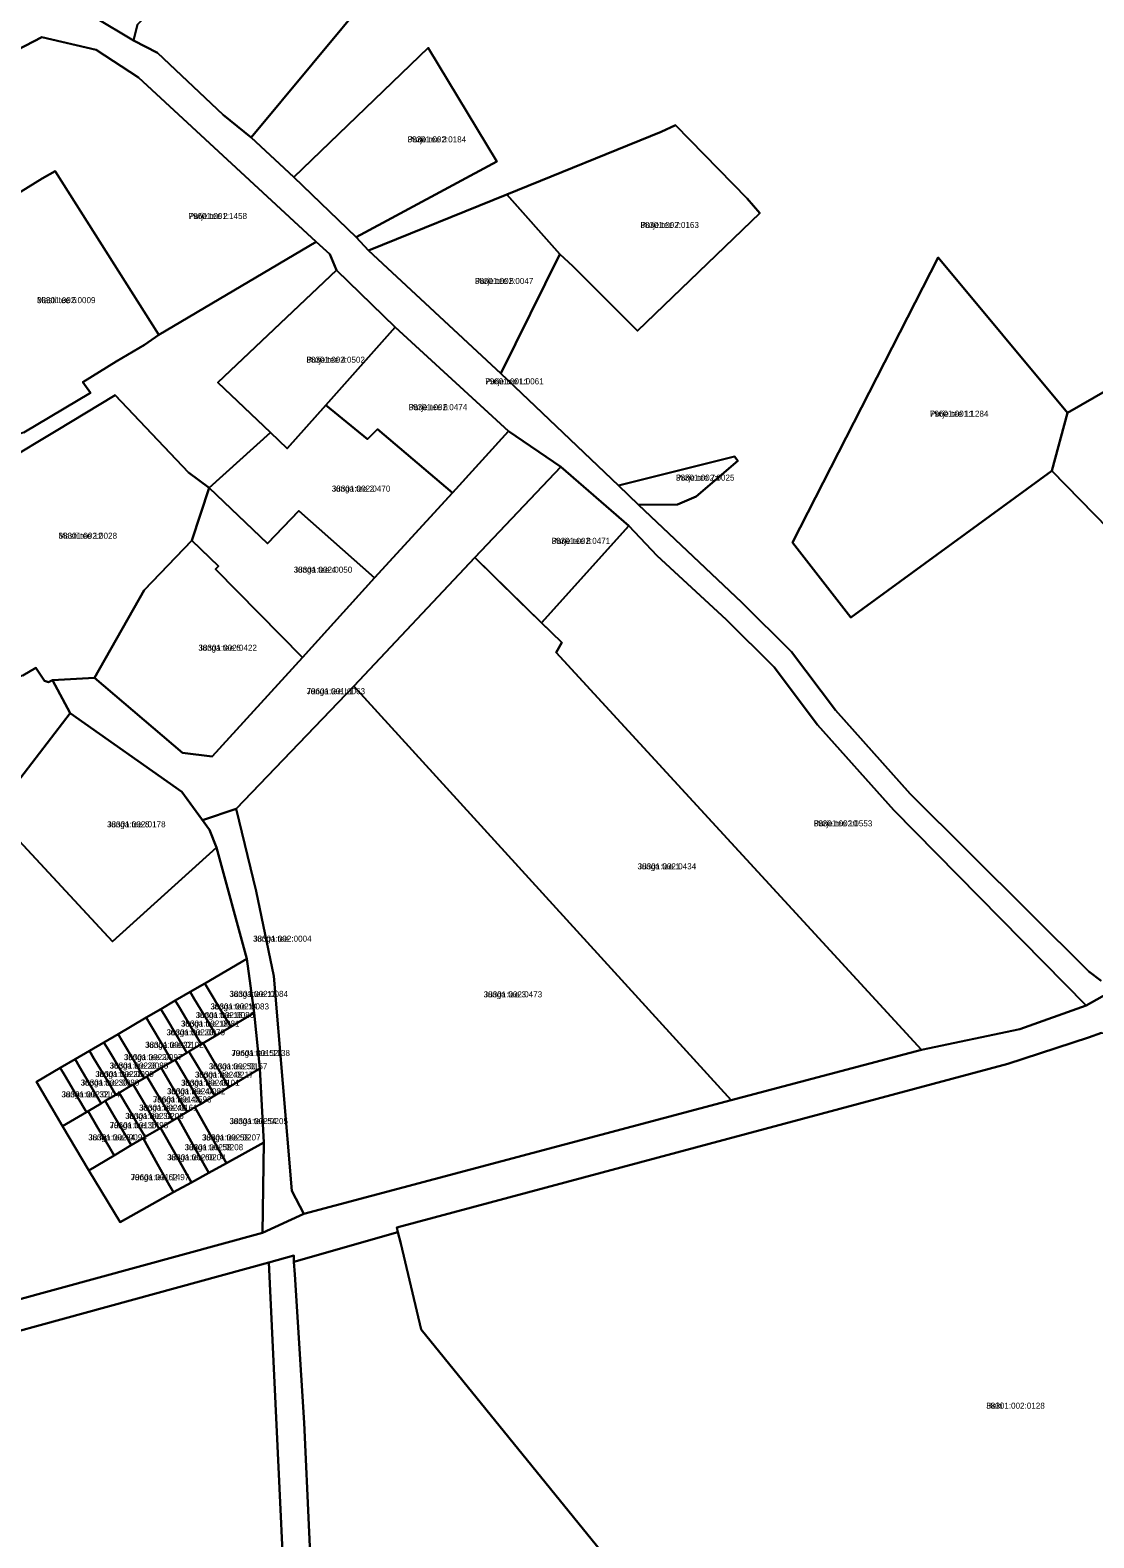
# Model space of a CAD drawing. Extents: x 625111 to 706696, y 6474150 to 6504223.
# Drawn here: x 638950.5 to 639214.1, y 6485129 to 6485502.8 of the extents above; entities that cross this region are included whole.
import ezdxf

# ---------------------------------------------------------------- set-up
doc = ezdxf.new("R2010")
doc.units = 0
for name, color, linetype in [('L_AADRESS', 7, 'Continuous'), ('PIIR', 7, 'Continuous'), ('TUNNUS', 7, 'Continuous')]:
    doc.layers.add(name, color=color, linetype=linetype)

msp = doc.modelspace()

# ---------------------------------------------------------------- linework, layer by layer
at = {"layer": 'PIIR'}
for points in [[(639010.64, 6485537.95), (639035.56, 6485512.65), (639005.26, 6485476.19), (638998.35, 6485481.82), (638982.04, 6485497.2), (638976.15, 6485500.27), (638977.1, 6485504.18)], [(639015.83, 6485466.34), (639049.18, 6485498.45), (639066.18, 6485470.28), (639031.32, 6485451.5)], [(639068.64, 6485462.05), (639106.89, 6485477.59), (639110.46, 6485479.24), (639128.18, 6485461.07), (639131.35, 6485457.43), (639101.01, 6485428.29), (639085.01, 6485444.3), (639081.76, 6485447.26)], [(638982.43, 6485427.28), (638978.84, 6485424.81), (638971.8, 6485420.65), (638963.59, 6485415.55), (638965.5, 6485412.9), (638948.95, 6485403.05), (638947.96, 6485402.69), (638946.97, 6485402.47), (638945.96, 6485402.38), (638944.88, 6485402.38), (638943.92, 6485402.7), (638942.97, 6485403.08), (638942.09, 6485403.64), (638941.29, 6485404.34), (638940.45, 6485405.39), (638921.96, 6485435.63), (638937.31, 6485455.82), (638938.31, 6485456.75), (638946.5, 6485461.77), (638953.47, 6485466.04), (638956.67, 6485467.85)], [(639034.4, 6485448.19), (639068.64, 6485462.05), (639081.76, 6485447.26), (639067.13, 6485417.7)], [(639203.71, 6485393.55), (639207.6, 6485407.89), (639283.19, 6485451.39), (639301.78, 6485411.96), (639278.22, 6485355.53), (639266.83, 6485328.96)], [(639203.71, 6485393.55), (639153.92, 6485357.21), (639139.42, 6485375.76), (639175.58, 6485446.47), (639207.6, 6485407.89)], [(638996.98, 6485415.46), (639026.45, 6485443.33), (639040.99, 6485429.13), (639023.8, 6485409.79), (639014.2, 6485399.09), (639010.04, 6485403.04)], [(639069.1, 6485403.36), (639055.15, 6485388.06), (639036.61, 6485403.91), (639034.14, 6485401.41), (639023.8, 6485409.79), (639040.99, 6485429.13)], [(638925.68, 6485378.85), (638936.93, 6485385.6), (638934.77, 6485390.22), (638944.32, 6485395.86), (638956.91, 6485403.45), (638971.58, 6485412.28), (638989.73, 6485393.14), (638994.84, 6485389.32), (638990.6, 6485376.31), (638978.8, 6485363.93), (638966.42, 6485342.25), (638956.01, 6485341.65), (638955.05, 6485341.15), (638954.02, 6485341.48), (638951.88, 6485344.74), (638948.66, 6485342.79), (638947.17, 6485342.22), (638944.9, 6485343.05), (638924.49, 6485375.18), (638924.28, 6485376.2), (638924.43, 6485377.27)], [(638994.84, 6485389.32), (639010.04, 6485403.04), (639014.2, 6485399.09), (639023.8, 6485409.79), (639034.14, 6485401.41), (639036.61, 6485403.91), (639055.15, 6485388.06), (639035.89, 6485367.01), (639017.13, 6485383.63), (639009.37, 6485375.54)], [(638960.45, 6485333.44), (638956.01, 6485341.65), (638966.42, 6485342.25), (638988.24, 6485323.64), (638995.61, 6485322.73), (639018, 6485347.28), (639035.89, 6485367.01), (639055.15, 6485388.06), (639069.1, 6485403.36), (639082.01, 6485394.58), (639060.68, 6485372.03), (639030.74, 6485340.14), (639001.53, 6485309.78), (638993.22, 6485306.96), (638988.09, 6485314)], [(639125.08, 6485397.14), (639125.89, 6485396.06), (639115.54, 6485387.19), (639110.95, 6485385.23), (639101.3, 6485385.1), (639096.3, 6485389.94)], [(639060.68, 6485372.03), (639082.01, 6485394.58), (639098.87, 6485379.9), (639077.27, 6485355.87)], [(638990.6, 6485376.31), (638994.84, 6485389.32), (639009.37, 6485375.54), (639017.13, 6485383.63), (639035.89, 6485367.01), (639018, 6485347.28), (638996.42, 6485369.13), (638997.15, 6485369.9)], [(639105.9, 6485372.5), (639122.99, 6485356.67), (639134.89, 6485344.87), (639145.62, 6485330.59), (639164.58, 6485309.39), (639212.2, 6485260.95), (639195.81, 6485255.15), (639171.42, 6485249.96), (639080.87, 6485348.54), (639082.28, 6485350.99), (639077.27, 6485355.87), (639098.87, 6485379.9)], [(638997.15, 6485369.9), (638996.42, 6485369.13), (639018, 6485347.28), (638995.61, 6485322.73), (638988.24, 6485323.64), (638966.42, 6485342.25), (638978.8, 6485363.93), (638990.6, 6485376.31)], [(639124.29, 6485237.5), (639030.74, 6485340.14), (639060.68, 6485372.03), (639071.48, 6485361.51), (639082.28, 6485350.99), (639080.87, 6485348.54), (639171.42, 6485249.96)], [(639018.3, 6485209.31), (639015.35, 6485215.07), (639010.93, 6485268.22), (639006.5, 6485289.35), (639001.53, 6485309.78), (639030.74, 6485340.14), (639124.29, 6485237.5)], [(638941.32, 6485308.7), (638960.45, 6485333.44), (638988.09, 6485314), (638994.99, 6485304.53), (638996.71, 6485300.14), (638970.95, 6485276.89)], [(638993.22, 6485306.96), (639001.53, 6485309.78), (639006.5, 6485289.35), (639010.93, 6485268.22), (639015.35, 6485215.07), (639018.3, 6485209.31), (639008.05, 6485204.62), (639008.46, 6485227), (639007.44, 6485245.37), (639006.05, 6485259.13), (639004.2, 6485272.57), (638996.71, 6485300.14), (638994.99, 6485304.53)], [(638993.78, 6485266.47), (639004.2, 6485272.57), (639006.05, 6485259.13), (639000.21, 6485255.68), (638997.85, 6485259.64), (638994.77, 6485264.81)], [(638990.19, 6485264.37), (638993.78, 6485266.47), (638994.77, 6485264.81), (638997.85, 6485259.64), (639000.21, 6485255.68), (638996.61, 6485253.55), (638994.26, 6485257.51), (638991.19, 6485262.68)], [(638986.48, 6485262.2), (638990.19, 6485264.37), (638991.19, 6485262.68), (638994.26, 6485257.51), (638996.61, 6485253.55), (638993.35, 6485251.63), (638992.91, 6485251.37), (638990.57, 6485255.31), (638987.5, 6485260.49)], [(638979.26, 6485257.98), (638982.89, 6485260.1), (638983.93, 6485258.36), (638987.01, 6485253.2), (638989.36, 6485249.27), (638986.44, 6485247.55), (638985.71, 6485247.12), (638983.38, 6485251.04), (638980.31, 6485256.21)], [(638982.89, 6485260.1), (638986.48, 6485262.2), (638987.5, 6485260.49), (638990.57, 6485255.31), (638992.91, 6485251.37), (638989.87, 6485249.57), (638989.36, 6485249.27), (638987.01, 6485253.2), (638983.93, 6485258.36)], [(639007.44, 6485245.37), (638999.74, 6485240.75), (638998.59, 6485242.7), (638995.67, 6485247.68), (638993.35, 6485251.63), (638996.61, 6485253.55), (639000.21, 6485255.68), (639006.05, 6485259.13)], [(638972.28, 6485253.9), (638979.26, 6485257.98), (638980.31, 6485256.21), (638983.38, 6485251.04), (638985.71, 6485247.12), (638982.97, 6485245.5), (638979.45, 6485243.42), (638978.73, 6485242.99), (638976.42, 6485246.9), (638973.36, 6485252.07)], [(638965.21, 6485249.75), (638968.78, 6485251.85), (638969.88, 6485250), (638972.95, 6485244.84), (638975.26, 6485240.95), (638972.58, 6485239.36), (638971.7, 6485238.84), (638969.39, 6485242.72), (638966.32, 6485247.88)], [(638968.78, 6485251.85), (638972.28, 6485253.9), (638973.36, 6485252.07), (638976.42, 6485246.9), (638978.73, 6485242.99), (638976.03, 6485241.4), (638975.26, 6485240.95), (638972.95, 6485244.84), (638969.88, 6485250)], [(638989.87, 6485249.57), (638992.91, 6485251.37), (638993.35, 6485251.63), (638995.67, 6485247.68), (638998.59, 6485242.7), (638999.74, 6485240.75), (638996.29, 6485238.7), (638995.13, 6485240.66), (638992.19, 6485245.64)], [(639042.34, 6485202.02), (639041.65, 6485204.78), (639041.41, 6485205.92), (639192.81, 6485246.5), (639212.83, 6485253.06), (639216.08, 6485254.18), (639220.87, 6485253.53), (639325.67, 6485146.73), (639324.92, 6485146.01), (639323.57, 6485144.72), (639323.54, 6485141.44), (639320.76, 6485131.95), (639215.62, 6485094.79), (639138.95, 6485067.85), (639047.4, 6485180.65)], [(638957.98, 6485245.52), (638961.62, 6485247.66), (638962.75, 6485245.76), (638965.82, 6485240.6), (638968.12, 6485236.73), (638964.87, 6485234.81), (638964.49, 6485234.58), (638962.19, 6485238.44), (638959.12, 6485243.6)], [(638961.62, 6485247.66), (638965.21, 6485249.75), (638966.32, 6485247.88), (638969.39, 6485242.72), (638971.7, 6485238.84), (638969.13, 6485237.32), (638968.12, 6485236.73), (638965.82, 6485240.6), (638962.75, 6485245.76)], [(638982.97, 6485245.5), (638985.71, 6485247.12), (638986.44, 6485247.55), (638988.75, 6485243.62), (638991.68, 6485238.63), (638992.85, 6485236.64), (638989.4, 6485234.59), (638988.22, 6485236.59), (638985.28, 6485241.58)], [(638986.44, 6485247.55), (638989.36, 6485249.27), (638989.87, 6485249.57), (638992.19, 6485245.64), (638995.13, 6485240.66), (638996.29, 6485238.7), (638992.85, 6485236.64), (638991.68, 6485238.63), (638988.75, 6485243.62)], [(638952.06, 6485242.06), (638957.98, 6485245.52), (638959.12, 6485243.6), (638962.19, 6485238.44), (638964.49, 6485234.58), (638958.49, 6485231.04)], [(638979.45, 6485243.42), (638982.97, 6485245.5), (638985.28, 6485241.58), (638988.22, 6485236.59), (638989.4, 6485234.59), (638985.87, 6485232.48), (638984.68, 6485234.51), (638981.75, 6485239.5)], [(638991.35, 6485235.77), (638992.85, 6485236.64), (638996.29, 6485238.7), (638999.74, 6485240.75), (639007.44, 6485245.37), (639008.46, 6485227), (638999.13, 6485221.88), (638998.1, 6485223.72), (638995.16, 6485228.97)], [(638972.58, 6485239.36), (638975.26, 6485240.95), (638976.03, 6485241.4), (638978.33, 6485237.49), (638981.26, 6485232.5), (638982.45, 6485230.44), (638979.01, 6485228.39), (638977.8, 6485230.46), (638974.87, 6485235.45)], [(638982.45, 6485230.44), (638981.26, 6485232.5), (638978.33, 6485237.49), (638976.03, 6485241.4), (638978.73, 6485242.99), (638979.45, 6485243.42), (638981.75, 6485239.5), (638984.68, 6485234.51), (638985.87, 6485232.48), (638982.85, 6485230.69)], [(638971.32, 6485223.81), (638970.08, 6485225.92), (638967.15, 6485230.91), (638964.87, 6485234.81), (638968.12, 6485236.73), (638969.13, 6485237.32), (638971.42, 6485233.42), (638974.35, 6485228.43), (638975.57, 6485226.35)], [(638969.13, 6485237.32), (638971.7, 6485238.84), (638972.58, 6485239.36), (638974.87, 6485235.45), (638977.8, 6485230.46), (638979.01, 6485228.39), (638978.48, 6485228.08), (638975.57, 6485226.35), (638974.35, 6485228.43), (638971.42, 6485233.42)], [(638958.49, 6485231.04), (638964.49, 6485234.58), (638964.87, 6485234.81), (638967.15, 6485230.91), (638970.08, 6485225.92), (638971.32, 6485223.81), (638965.07, 6485220.09)], [(638982.85, 6485230.69), (638985.87, 6485232.48), (638987.09, 6485233.23), (638990.82, 6485226.54), (638993.76, 6485221.27), (638994.76, 6485219.48), (638990.46, 6485217.11), (638989.48, 6485218.86), (638986.52, 6485224.14)], [(638987.09, 6485233.23), (638989.4, 6485234.59), (638991.35, 6485235.77), (638995.16, 6485228.97), (638998.1, 6485223.72), (638999.13, 6485221.88), (638994.76, 6485219.48), (638993.76, 6485221.27), (638990.82, 6485226.54)], [(638978.48, 6485228.08), (638979.01, 6485228.39), (638982.45, 6485230.44), (638982.85, 6485230.69), (638986.52, 6485224.14), (638989.48, 6485218.86), (638990.46, 6485217.11), (638986.03, 6485214.67), (638985.08, 6485216.37), (638982.09, 6485221.66)], [(638971.32, 6485223.81), (638975.57, 6485226.35), (638978.48, 6485228.08), (638982.09, 6485221.66), (638985.08, 6485216.37), (638986.03, 6485214.67), (638972.83, 6485207.29), (638965.07, 6485220.09)], [(638847.7, 6485162.63), (638860.71, 6485161.51), (638876.99, 6485161.83), (638890.17, 6485164.52), (639009.68, 6485197.31), (639015.85, 6485066.04), (638938.01, 6485026.87)]]:
    msp.add_lwpolyline(points, close=True, dxfattribs=at)
for points in [[(639215.93, 6485267.07), (639212.92, 6485269.38), (639168.64, 6485313.48), (639150.08, 6485334.24), (639139.22, 6485348.69), (639126.92, 6485360.88), (639101.3, 6485385.1), (639110.95, 6485385.23), (639115.54, 6485387.19), (639125.89, 6485396.06), (639125.08, 6485397.14), (639096.3, 6485389.94), (639067.13, 6485417.7), (639081.76, 6485447.26), (639085.01, 6485444.3), (639101.01, 6485428.29), (639131.35, 6485457.43), (639128.18, 6485461.07), (639110.46, 6485479.24), (639106.89, 6485477.59), (639068.64, 6485462.05), (639034.4, 6485448.19), (639031.32, 6485451.5), (639066.18, 6485470.28), (639049.18, 6485498.45), (639015.83, 6485466.34), (639005.26, 6485476.19), (639035.56, 6485512.65)], [(639223.56, 6485267.38), (639212.2, 6485260.95), (639164.58, 6485309.39), (639145.62, 6485330.59), (639134.89, 6485344.87), (639122.99, 6485356.67), (639105.9, 6485372.5), (639098.87, 6485379.9), (639082.01, 6485394.58), (639069.1, 6485403.36), (639040.99, 6485429.13), (639026.45, 6485443.33), (639024.74, 6485447.28), (639021.42, 6485450.35), (638977.35, 6485491.09), (638966.87, 6485497.91), (638953.41, 6485501.05), (638945.14, 6485496.81), (638942.22, 6485489.86), (638943.68, 6485483.71), (638938.35, 6485482.36), (638903, 6485489.78), (638912.12, 6485506.89)], [(638977.1, 6485504.18), (638976.15, 6485500.27), (638966.47, 6485506.01)], [(638966.47, 6485506.01), (638976.15, 6485500.27), (638982.04, 6485497.2), (638998.35, 6485481.82), (639005.26, 6485476.19), (639015.83, 6485466.34), (639031.32, 6485451.5), (639034.4, 6485448.19), (639067.13, 6485417.7), (639096.3, 6485389.94), (639101.3, 6485385.1), (639126.92, 6485360.88), (639139.22, 6485348.69), (639150.08, 6485334.24), (639168.64, 6485313.48), (639212.92, 6485269.38), (639215.93, 6485267.07)], [(638945.14, 6485496.81), (638953.41, 6485501.05), (638966.87, 6485497.91), (638977.35, 6485491.09), (639021.42, 6485450.35), (638982.43, 6485427.28), (638956.67, 6485467.85), (638953.47, 6485466.04), (638946.5, 6485461.77)], [(638948.95, 6485403.05), (638965.5, 6485412.9), (638963.59, 6485415.55), (638971.8, 6485420.65), (638978.84, 6485424.81), (638982.43, 6485427.28), (639021.42, 6485450.35), (639024.74, 6485447.28), (639026.45, 6485443.33), (638996.98, 6485415.46), (639010.04, 6485403.04), (638994.84, 6485389.32), (638989.73, 6485393.14), (638971.58, 6485412.28), (638956.91, 6485403.45), (638944.32, 6485395.86)], [(639283.19, 6485451.39), (639207.6, 6485407.89), (639175.58, 6485446.47), (639139.42, 6485375.76), (639153.92, 6485357.21), (639203.71, 6485393.55), (639266.83, 6485328.96)], [(638948.66, 6485342.79), (638951.88, 6485344.74), (638954.02, 6485341.48), (638955.05, 6485341.15), (638956.01, 6485341.65), (638960.45, 6485333.44), (638941.32, 6485308.7)], [(638941.32, 6485308.7), (638970.95, 6485276.89), (638996.71, 6485300.14), (639004.2, 6485272.57), (638993.78, 6485266.47), (638990.19, 6485264.37), (638986.48, 6485262.2), (638982.89, 6485260.1), (638979.26, 6485257.98), (638972.28, 6485253.9), (638968.78, 6485251.85), (638965.21, 6485249.75), (638961.62, 6485247.66), (638957.98, 6485245.52), (638952.06, 6485242.06), (638958.49, 6485231.04), (638965.07, 6485220.09), (638972.83, 6485207.29), (638986.03, 6485214.67), (638990.46, 6485217.11), (638994.76, 6485219.48), (638999.13, 6485221.88), (639008.46, 6485227), (639008.05, 6485204.62), (638905.91, 6485176.68)], [(638905.91, 6485176.68), (639008.05, 6485204.62), (639018.3, 6485209.31), (639124.29, 6485237.5), (639171.42, 6485249.96), (639195.81, 6485255.15), (639212.2, 6485260.95), (639223.56, 6485267.38)], [(639216.08, 6485254.18), (639212.83, 6485253.06), (639192.81, 6485246.5), (639041.41, 6485205.92), (639041.65, 6485204.78), (639015.86, 6485197.43), (639015.83, 6485198.98), (639009.68, 6485197.31), (638890.17, 6485164.52)], [(639220.14, 6485084.24), (639206.96, 6485079.44), (639141.14, 6485053.95), (639101.54, 6485039.59), (639069.15, 6485028.91), (639081.2, 6484970.65), (639084.28, 6484962.94), (639028.25, 6484940.61), (639024.64, 6485021.99), (639018.45, 6485157.55), (639016.1, 6485194.29), (639015.86, 6485197.43), (639041.65, 6485204.78), (639042.34, 6485202.02), (639047.4, 6485180.65), (639138.95, 6485067.85), (639215.62, 6485094.79)], [(639015.85, 6485066.04), (639009.68, 6485197.31), (639015.83, 6485198.98), (639015.86, 6485197.43), (639016.1, 6485194.29), (639018.45, 6485157.55), (639024.64, 6485021.99)]]:
    msp.add_lwpolyline(points, dxfattribs=at)

# ---------------------------------------------------------------- texts
at = {"layer": 'L_AADRESS'}
for s, p in [('Purje tee 3', (639044.07, 6485474.98)), ('Purje tee 2', (638989.76, 6485455.99)), ('Purje tee 7', (639101.76, 6485453.76)), ('Purje tee 5', (639060.72, 6485439.88)), ('Masti tee 5', (638952.2, 6485435.12)), ('Purje tee 4', (639018.98, 6485420.35)), ('Purje tee L1', (639063.28, 6485414.99)), ('Purje tee 6', (639044.33, 6485408.59)), ('Purje tee 11', (639173.51, 6485406.97)), ('Junga tee 2', (639025.28, 6485388.4)), ('Purje tee 7a', (639110.57, 6485391.12)), ('Masti tee 12', (638957.54, 6485376.71)), ('Purje tee 8', (639079.77, 6485375.44)), ('Junga tee 4', (639015.84, 6485368.3)), ('Junga tee 6', (638992.21, 6485348.94)), ('Junga tee L1', (639019.01, 6485338.17)), ('Junga tee 8', (638969.57, 6485305.17)), ('Purje tee 10', (639144.74, 6485305.39)), ('Junga tee 1', (639101.08, 6485294.75)), ('Junga tee', (639005.76, 6485276.81)), ('Junga tee 12', (638999.91, 6485263.12)), ('Junga tee 3', (639062.91, 6485263.01)), ('Junga tee 16', (638991.54, 6485257.88)), ('Junga tee 14', (638995.2, 6485260.01)), ('Junga tee 20', (638984.31, 6485253.6)), ('Junga tee 18', (638987.9, 6485255.76)), ('Junga tee 22', (638979, 6485250.49)), ('Junga tee 24', (638973.75, 6485247.44)), ('Junga tee 52', (639000.39, 6485248.47)), ('Junga tee 28', (638966.66, 6485243.25)), ('Junga tee 26', (638970.23, 6485245.35)), ('Junga tee 48', (638991.36, 6485243.1)), ('Junga tee 50', (638994.8, 6485245.18)), ('Junga tee 30', (638963.05, 6485241.13)), ('Junga tee 44', (638984.43, 6485238.99)), ('Junga tee 46', (638987.91, 6485241.08)), ('Junga tee 32', (638958.28, 6485238.22)), ('Junga tee 40', (638977.52, 6485234.91)), ('Junga tee 42', (638980.95, 6485236.95)), ('Junga tee 38', (638974.07, 6485232.86)), ('Junga tee 54', (638999.91, 6485231.58)), ('Junga tee 34', (638964.91, 6485227.56)), ('Junga tee 36', (638970.22, 6485230.57)), ('Junga tee 56', (638993.11, 6485227.53)), ('Junga tee 58', (638988.8, 6485225.11)), ('Junga tee 60', (638984.47, 6485222.62)), ('Junga tee 62', (638975.43, 6485217.68)), ('Heki', (639187.49, 6485161.02))]:
    msp.add_text(s, height=1.5, dxfattribs=at).set_placement(p)
at = {"layer": 'TUNNUS'}
for s, p in [('38301:002:0184', (639044.07, 6485474.98)), ('79601:001:1458', (638989.76, 6485455.99)), ('38301:002:0163', (639101.76, 6485453.76)), ('38301:002:0047', (639060.72, 6485439.88)), ('38301:002:0009', (638952.2, 6485435.12)), ('38301:002:0502', (639018.98, 6485420.35)), ('79601:001:0061', (639063.28, 6485414.99)), ('38301:002:0474', (639044.33, 6485408.59)), ('79601:001:1284', (639173.51, 6485406.97)), ('38301:002:0470', (639025.28, 6485388.4)), ('38301:002:0025', (639110.57, 6485391.12)), ('38301:002:0028', (638957.54, 6485376.71)), ('38301:002:0471', (639079.77, 6485375.44)), ('38301:002:0050', (639015.84, 6485368.3)), ('38301:002:0422', (638992.21, 6485348.94)), ('79601:001:0063', (639019.01, 6485338.17)), ('38301:002:0178', (638969.57, 6485305.17)), ('38301:002:0553', (639144.74, 6485305.39)), ('38301:002:0434', (639101.08, 6485294.75)), ('38301:002:0004', (639005.76, 6485276.81)), ('38301:002:0084', (638999.91, 6485263.12)), ('38301:002:0473', (639062.91, 6485263.01)), ('38301:002:0086', (638991.54, 6485257.88)), ('38301:002:0083', (638995.2, 6485260.01)), ('38301:002:0079', (638984.31, 6485253.6)), ('38301:002:0081', (638987.9, 6485255.76)), ('38301:002:0102', (638979, 6485250.49)), ('38301:002:0097', (638973.75, 6485247.44)), ('79601:001:1138', (639000.39, 6485248.47)), ('38301:002:0099', (638966.66, 6485243.25)), ('38301:002:0085', (638970.23, 6485245.35)), ('38301:002:0217', (638991.36, 6485243.1)), ('38301:002:0157', (638994.8, 6485245.18)), ('38301:002:0080', (638963.05, 6485241.13)), ('38301:002:0082', (638984.43, 6485238.99)), ('38301:002:0101', (638987.91, 6485241.08)), ('38301:002:0104', (638958.28, 6485238.22)), ('38301:002:0161', (638977.52, 6485234.91)), ('79601:001:1593', (638980.95, 6485236.95)), ('38301:002:0206', (638974.07, 6485232.86)), ('38301:002:0205', (638999.91, 6485231.58)), ('38301:002:0094', (638964.91, 6485227.56)), ('79601:001:1498', (638970.22, 6485230.57)), ('38301:002:0207', (638993.11, 6485227.53)), ('38301:002:0208', (638988.8, 6485225.11)), ('38301:002:0204', (638984.47, 6485222.62)), ('79601:001:1497', (638975.43, 6485217.68)), ('38301:002:0128', (639187.49, 6485161.02))]:
    msp.add_text(s, height=1.5, dxfattribs=at).set_placement(p)

doc.saveas('drawing.dxf')
